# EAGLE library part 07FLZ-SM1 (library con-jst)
CONNECTOR
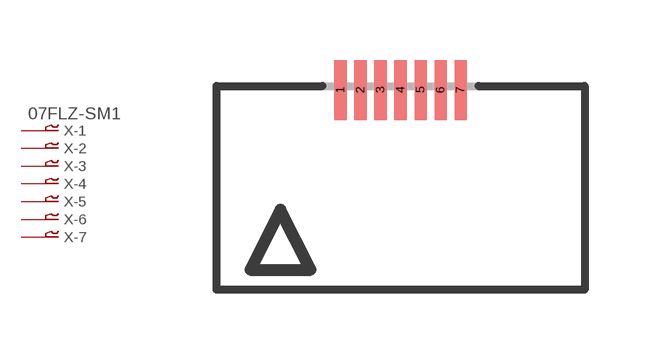
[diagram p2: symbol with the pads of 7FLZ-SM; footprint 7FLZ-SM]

Designator prefix X; gates -1=P-VN -2=P-N -3=P-N -4=P-N -5=P-N -6=P-N -7=P-N

## 07FLZ-SM1 (OC_FARNELL: unknown; OC_NEWARK: unknown)  [7FLZ-SM]
1  -1:1  pas
2  -2:1  pas
3  -3:1  pas
4  -4:1  pas
5  -5:1  pas
6  -6:1  pas
7  -7:1  pas

## Footprint 7FLZ-SM (pad centres in mm)
CONNECTOR
smd 0.3 x 1.5: 1 -1.5,2.5; 2 -1,2.5; 3 -0.5,2.5; 4 0,2.5; 5 0.5,2.5; 6 1,2.5; 7 1.5,2.5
